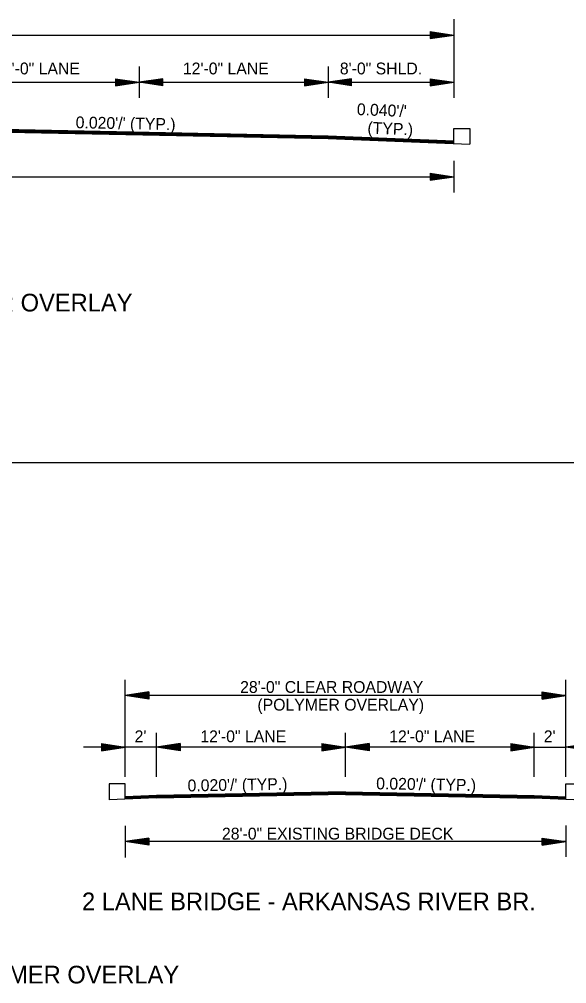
# Model space of a CAD drawing. Extents: x 550980 to 1930787, y -1972975 to 596640.
# Drawn here: x 551685 to 552033, y -1954087 to -1953474 of the extents above; entities that cross this region are included whole.
import ezdxf

# ---------------------------------------------------------------- set-up
doc = ezdxf.new("R2010")
doc.units = 0
doc.layers.add('R_Border', color=7, linetype='Continuous')
doc.layers.add('R_Draft', color=7, linetype='Continuous')

msp = doc.modelspace()

# ---------------------------------------------------------------- linework, layer by layer
at = {"layer": 'R_Border'}
for p, q in [((551961.34, -1953474.37), (551961.34, -1953524.37)), ((551946.34, -1953482.12), (551961.34, -1953484.37)), ((551946.34, -1953482.12), (551946.34, -1953486.62)), ((551946.34, -1953482.5), (551958.83, -1953484.37)), ((551201.34, -1953484.37), (551961.34, -1953484.37)), ((551946.34, -1953482.88), (551956.25, -1953484.37)), ((551946.34, -1953483.25), (551953.76, -1953484.37)), ((551946.34, -1953483.64), (551951.21, -1953484.37)), ((551946.34, -1953484.02), (551948.71, -1953484.37)), ((551946.34, -1953486.62), (551961.34, -1953484.37)), ((551946.34, -1953485.11), (551951.21, -1953484.37)), ((551946.34, -1953485.86), (551956.25, -1953484.37)), ((551946.34, -1953486.25), (551958.83, -1953484.37)), ((551946.34, -1953485.49), (551953.76, -1953484.37)), ((551946.34, -1953484.72), (551948.71, -1953484.37)), ((551761.34, -1953504.37), (551761.34, -1953524.37)), ((551881.34, -1953504.37), (551881.34, -1953524.37)), ((551746.34, -1953512.12), (551761.34, -1953514.37)), ((551746.34, -1953512.12), (551746.34, -1953516.62)), ((551746.34, -1953512.5), (551758.83, -1953514.37)), ((551746.34, -1953512.88), (551756.25, -1953514.37)), ((551776.34, -1953512.12), (551761.34, -1953514.37)), ((551776.34, -1953512.5), (551763.84, -1953514.37)), ((551776.34, -1953512.88), (551766.42, -1953514.37)), ((551776.34, -1953516.62), (551776.34, -1953512.12)), ((551866.34, -1953512.12), (551881.34, -1953514.37)), ((551866.34, -1953512.12), (551866.34, -1953516.62)), ((551866.34, -1953512.5), (551878.83, -1953514.37)), ((551866.34, -1953512.88), (551876.25, -1953514.37)), ((551896.34, -1953512.12), (551881.34, -1953514.37)), ((551896.34, -1953512.5), (551883.84, -1953514.37)), ((551896.34, -1953512.88), (551886.42, -1953514.37)), ((551896.34, -1953516.62), (551896.34, -1953512.12)), ((551946.34, -1953512.12), (551961.34, -1953514.37)), ((551946.34, -1953512.12), (551946.34, -1953516.62)), ((551946.34, -1953512.5), (551958.83, -1953514.37)), ((551946.34, -1953512.88), (551956.25, -1953514.37)), ((551201.34, -1953514.37), (551961.34, -1953514.37)), ((551746.34, -1953513.25), (551753.76, -1953514.37)), ((551746.34, -1953513.64), (551751.21, -1953514.37)), ((551746.34, -1953514.02), (551748.71, -1953514.37)), ((551746.34, -1953516.62), (551761.34, -1953514.37)), ((551746.34, -1953515.11), (551751.21, -1953514.37)), ((551746.34, -1953515.86), (551756.25, -1953514.37)), ((551746.34, -1953516.25), (551758.83, -1953514.37)), ((551746.34, -1953515.49), (551753.76, -1953514.37)), ((551746.34, -1953514.72), (551748.71, -1953514.37)), ((551776.34, -1953516.62), (551761.34, -1953514.37)), ((551776.34, -1953516.25), (551763.84, -1953514.37)), ((551776.34, -1953515.86), (551766.42, -1953514.37)), ((551776.34, -1953513.25), (551768.92, -1953514.37)), ((551776.34, -1953515.49), (551768.92, -1953514.37)), ((551776.34, -1953513.64), (551771.46, -1953514.37)), ((551776.34, -1953515.1), (551771.46, -1953514.37)), ((551776.34, -1953514.02), (551773.97, -1953514.37)), ((551776.34, -1953514.72), (551773.97, -1953514.37)), ((551866.34, -1953513.25), (551873.76, -1953514.37)), ((551866.34, -1953513.64), (551871.21, -1953514.37)), ((551866.34, -1953514.02), (551868.71, -1953514.37)), ((551866.34, -1953516.62), (551881.34, -1953514.37)), ((551866.34, -1953515.11), (551871.21, -1953514.37)), ((551866.34, -1953515.86), (551876.25, -1953514.37)), ((551866.34, -1953516.25), (551878.83, -1953514.37)), ((551866.34, -1953515.49), (551873.76, -1953514.37)), ((551866.34, -1953514.72), (551868.71, -1953514.37)), ((551896.34, -1953516.62), (551881.34, -1953514.37)), ((551896.34, -1953516.25), (551883.84, -1953514.37)), ((551896.34, -1953515.86), (551886.42, -1953514.37)), ((551896.34, -1953513.25), (551888.92, -1953514.37)), ((551896.34, -1953515.49), (551888.92, -1953514.37)), ((551896.34, -1953513.64), (551891.46, -1953514.37)), ((551896.34, -1953515.1), (551891.46, -1953514.37)), ((551896.34, -1953514.02), (551893.97, -1953514.37)), ((551896.34, -1953514.72), (551893.97, -1953514.37)), ((551946.34, -1953513.25), (551953.76, -1953514.37)), ((551946.34, -1953513.64), (551951.21, -1953514.37)), ((551946.34, -1953514.02), (551948.71, -1953514.37)), ((551946.34, -1953516.62), (551961.34, -1953514.37)), ((551946.34, -1953515.11), (551951.21, -1953514.37)), ((551946.34, -1953515.86), (551956.25, -1953514.37)), ((551946.34, -1953516.25), (551958.83, -1953514.37)), ((551946.34, -1953515.49), (551953.76, -1953514.37)), ((551946.34, -1953514.72), (551948.71, -1953514.37)), ((551961.34, -1953553.07), (551961.34, -1953543.66)), ((551961.34, -1953543.66), (551971.51, -1953543.66)), ((551971.51, -1953543.66), (551971.51, -1953553.78)), ((551961.34, -1953564.37), (551961.34, -1953584.37)), ((551201.34, -1953574.37), (551961.34, -1953574.37)), ((551946.34, -1953572.12), (551961.34, -1953574.37)), ((551946.34, -1953572.12), (551946.34, -1953576.62)), ((551946.34, -1953572.5), (551958.83, -1953574.37)), ((551946.34, -1953572.88), (551956.25, -1953574.37)), ((551946.34, -1953573.25), (551953.76, -1953574.37)), ((551946.34, -1953573.64), (551951.21, -1953574.37)), ((551946.34, -1953574.02), (551948.71, -1953574.37)), ((551946.34, -1953576.62), (551961.34, -1953574.37)), ((551946.34, -1953575.11), (551951.21, -1953574.37)), ((551946.34, -1953575.86), (551956.25, -1953574.37)), ((551946.34, -1953576.25), (551958.83, -1953574.37)), ((551946.34, -1953575.49), (551953.76, -1953574.37)), ((551946.34, -1953574.72), (551948.71, -1953574.37)), ((551008.97, -1953755.99), (552070.24, -1953755.99)), ((551742.24, -1953960.14), (551742.24, -1953970.25)), ((551752.41, -1953960.14), (551742.24, -1953960.14)), ((551752.41, -1953969.54), (551752.41, -1953960.14)), ((552032.41, -1953969.54), (552032.41, -1953960.14)), ((552032.41, -1953960.14), (552042.58, -1953960.14))]:
    msp.add_line(p, q, dxfattribs=at)
for points in [[(551201.34, -1953551.57), (551281.34, -1953548.37), (551581.34, -1953542.37), (551881.34, -1953548.37), (551961.34, -1953551.57)], [(551201.34, -1953551.87), (551281.34, -1953548.67), (551581.34, -1953542.67), (551881.34, -1953548.67), (551961.34, -1953551.87)], [(551201.34, -1953552.17), (551281.34, -1953548.97), (551581.34, -1953542.97), (551881.34, -1953548.97), (551961.34, -1953552.17)], [(551201.34, -1953552.47), (551281.34, -1953549.27), (551581.34, -1953543.27), (551881.34, -1953549.27), (551961.34, -1953552.47)], [(551201.34, -1953552.77), (551281.34, -1953549.57), (551581.34, -1953543.57), (551881.34, -1953549.57), (551961.34, -1953552.77)], [(551191.17, -1953553.78), (551281.34, -1953550.17), (551581.34, -1953544.17), (551881.34, -1953550.17), (551971.51, -1953553.78)], [(551201.34, -1953553.07), (551281.34, -1953549.87), (551581.34, -1953543.87), (551881.34, -1953549.87), (551961.34, -1953553.07)]]:
    msp.add_lwpolyline(points, dxfattribs=at)
at = {"layer": 'R_Draft'}
for p, q in [((551752.41, -1953955.6), (551752.41, -1953894.11)), ((552032.41, -1953955.6), (552032.41, -1953894.11)), ((551767.41, -1953901.75), (551752.41, -1953904)), ((552032.41, -1953904), (551752.41, -1953904)), ((551767.41, -1953906.25), (551752.41, -1953904)), ((551767.41, -1953902.13), (551754.92, -1953904)), ((551767.41, -1953905.88), (551754.92, -1953904)), ((551767.41, -1953902.51), (551757.5, -1953904)), ((551767.41, -1953905.49), (551757.5, -1953904)), ((551767.41, -1953902.88), (551759.99, -1953904)), ((551767.41, -1953905.12), (551759.99, -1953904)), ((551767.41, -1953903.27), (551762.54, -1953904)), ((551767.41, -1953904.74), (551762.54, -1953904)), ((551767.41, -1953903.65), (551765.04, -1953904)), ((551767.41, -1953904.35), (551765.04, -1953904)), ((551767.41, -1953901.75), (551767.41, -1953906.25)), ((552017.41, -1953901.75), (552032.41, -1953904)), ((552017.41, -1953906.25), (552017.41, -1953901.75)), ((552017.41, -1953902.13), (552029.91, -1953904)), ((552017.41, -1953902.51), (552027.33, -1953904)), ((552017.41, -1953902.88), (552024.83, -1953904)), ((552017.41, -1953903.27), (552022.29, -1953904)), ((552017.41, -1953903.65), (552019.78, -1953904)), ((552017.41, -1953906.25), (552032.41, -1953904)), ((552017.41, -1953904.73), (552022.29, -1953904)), ((552017.41, -1953905.49), (552027.33, -1953904)), ((552017.41, -1953905.88), (552029.91, -1953904)), ((552017.41, -1953905.12), (552024.83, -1953904)), ((552017.41, -1953904.35), (552019.78, -1953904)), ((551772.41, -1953955.6), (551772.41, -1953927.64)), ((551892.41, -1953955.6), (551892.41, -1953927.64)), ((552012.41, -1953955.6), (552012.41, -1953927.64)), ((551737.41, -1953934.58), (551752.41, -1953936.83)), ((551737.41, -1953934.58), (551737.41, -1953939.08)), ((551737.41, -1953934.96), (551749.91, -1953936.83)), ((551737.41, -1953935.34), (551747.33, -1953936.83)), ((551737.41, -1953935.72), (551744.83, -1953936.83)), ((551787.41, -1953934.58), (551772.41, -1953936.83)), ((551787.41, -1953934.96), (551774.92, -1953936.83)), ((551787.41, -1953935.34), (551777.5, -1953936.83)), ((551787.41, -1953935.72), (551779.99, -1953936.83)), ((551787.41, -1953934.58), (551787.41, -1953939.08)), ((551877.41, -1953934.58), (551892.41, -1953936.83)), ((551877.41, -1953934.58), (551877.41, -1953939.08)), ((551877.41, -1953934.96), (551889.91, -1953936.83)), ((551877.41, -1953935.34), (551887.33, -1953936.83)), ((551877.41, -1953935.72), (551884.83, -1953936.83)), ((551907.41, -1953934.58), (551892.41, -1953936.83)), ((551907.41, -1953934.96), (551894.92, -1953936.83)), ((551907.41, -1953935.34), (551897.5, -1953936.83)), ((551907.41, -1953935.72), (551899.99, -1953936.83)), ((551907.41, -1953934.58), (551907.41, -1953939.08)), ((551997.41, -1953934.58), (552012.41, -1953936.83)), ((551997.41, -1953934.58), (551997.41, -1953939.08)), ((551997.41, -1953934.96), (552009.91, -1953936.83)), ((551997.41, -1953935.34), (552007.33, -1953936.83)), ((551997.41, -1953935.72), (552004.83, -1953936.83)), ((552047.41, -1953934.58), (552032.41, -1953936.83)), ((551752.41, -1953936.83), (551725.89, -1953936.83)), ((551737.41, -1953936.11), (551742.29, -1953936.83)), ((551737.41, -1953936.48), (551739.78, -1953936.83)), ((551737.41, -1953939.08), (551752.41, -1953936.83)), ((551737.41, -1953937.57), (551742.29, -1953936.83)), ((551737.41, -1953938.33), (551747.33, -1953936.83)), ((551737.41, -1953938.71), (551749.91, -1953936.83)), ((551737.41, -1953937.95), (551744.83, -1953936.83)), ((551737.41, -1953937.19), (551739.78, -1953936.83)), ((551772.41, -1953936.83), (551752.41, -1953936.83)), ((551892.41, -1953936.83), (551772.41, -1953936.83)), ((551787.41, -1953939.08), (551772.41, -1953936.83)), ((551787.41, -1953938.71), (551774.92, -1953936.83)), ((551787.41, -1953938.33), (551777.5, -1953936.83)), ((551787.41, -1953937.95), (551779.99, -1953936.83)), ((551787.41, -1953936.11), (551782.54, -1953936.83)), ((551787.41, -1953937.57), (551782.54, -1953936.83)), ((551787.41, -1953936.48), (551785.04, -1953936.83)), ((551787.41, -1953937.19), (551785.04, -1953936.83)), ((551877.41, -1953936.11), (551882.29, -1953936.83)), ((551877.41, -1953936.48), (551879.78, -1953936.83)), ((551877.41, -1953939.08), (551892.41, -1953936.83)), ((551877.41, -1953937.57), (551882.29, -1953936.83)), ((551877.41, -1953938.33), (551887.33, -1953936.83)), ((551877.41, -1953938.71), (551889.91, -1953936.83)), ((551877.41, -1953937.95), (551884.83, -1953936.83)), ((551877.41, -1953937.19), (551879.78, -1953936.83)), ((552012.41, -1953936.83), (551892.41, -1953936.83)), ((551907.41, -1953939.08), (551892.41, -1953936.83)), ((551907.41, -1953938.71), (551894.92, -1953936.83)), ((551907.41, -1953938.33), (551897.5, -1953936.83)), ((551907.41, -1953937.95), (551899.99, -1953936.83)), ((551907.41, -1953936.11), (551902.54, -1953936.83)), ((551907.41, -1953937.57), (551902.54, -1953936.83)), ((551907.41, -1953936.48), (551905.04, -1953936.83)), ((551907.41, -1953937.19), (551905.04, -1953936.83)), ((551997.41, -1953936.11), (552002.29, -1953936.83)), ((551997.41, -1953936.48), (551999.78, -1953936.83)), ((551997.41, -1953939.08), (552012.41, -1953936.83)), ((551997.41, -1953937.57), (552002.29, -1953936.83)), ((551997.41, -1953938.33), (552007.33, -1953936.83)), ((551997.41, -1953938.71), (552009.91, -1953936.83)), ((551997.41, -1953937.95), (552004.83, -1953936.83)), ((551997.41, -1953937.19), (551999.78, -1953936.83)), ((552012.41, -1953936.83), (552032.41, -1953936.83)), ((552047.41, -1953939.08), (552032.41, -1953936.83)), ((552058.93, -1953936.83), (552032.41, -1953936.83)), ((551892.41, -1953965.14), (551772.41, -1953967.54)), ((551892.41, -1953965.44), (551772.41, -1953967.84)), ((551892.41, -1953965.74), (551772.41, -1953968.14)), ((551892.41, -1953966.04), (551772.41, -1953968.44)), ((551892.41, -1953966.34), (551772.41, -1953968.74)), ((551892.41, -1953965.14), (552012.41, -1953967.54)), ((551892.41, -1953965.44), (552012.41, -1953967.84)), ((551892.41, -1953965.74), (552012.41, -1953968.14)), ((551892.41, -1953966.04), (552012.41, -1953968.44)), ((551892.41, -1953966.34), (552012.41, -1953968.74)), ((551772.41, -1953969.04), (551742.24, -1953970.25)), ((551772.41, -1953967.54), (551752.41, -1953968.34)), ((551772.41, -1953967.84), (551752.41, -1953968.64)), ((551772.41, -1953968.14), (551752.41, -1953968.94)), ((551772.41, -1953968.44), (551752.41, -1953969.24)), ((551772.41, -1953968.74), (551752.41, -1953969.54)), ((551892.41, -1953966.64), (551772.41, -1953969.04)), ((551892.41, -1953966.81), (551772.41, -1953969.21)), ((551892.41, -1953966.64), (552012.41, -1953969.04)), ((551892.41, -1953966.81), (552012.41, -1953969.21)), ((552012.41, -1953967.54), (552032.41, -1953968.34)), ((552012.41, -1953967.84), (552032.41, -1953968.64)), ((552012.41, -1953968.14), (552032.41, -1953968.94)), ((552012.41, -1953968.44), (552032.41, -1953969.24)), ((552012.41, -1953968.74), (552032.41, -1953969.54)), ((552012.41, -1953969.04), (552042.58, -1953970.25)), ((551752.41, -1953986.8), (551752.41, -1954006.8)), ((552032.41, -1953986.55), (552032.41, -1954006.55)), ((551767.41, -1953994.55), (551752.41, -1953996.8)), ((551767.41, -1953999.05), (551752.41, -1953996.8)), ((552032.41, -1953996.8), (551752.41, -1953996.8)), ((551767.41, -1953994.93), (551754.92, -1953996.8)), ((551767.41, -1953998.68), (551754.92, -1953996.8)), ((551767.41, -1953995.31), (551757.5, -1953996.8)), ((551767.41, -1953998.29), (551757.5, -1953996.8)), ((551767.41, -1953995.68), (551759.99, -1953996.8)), ((551767.41, -1953997.92), (551759.99, -1953996.8)), ((551767.41, -1953996.07), (551762.54, -1953996.8)), ((551767.41, -1953997.54), (551762.54, -1953996.8)), ((551767.41, -1953996.45), (551765.04, -1953996.8)), ((551767.41, -1953997.15), (551765.04, -1953996.8)), ((551767.41, -1953994.55), (551767.41, -1953999.05)), ((552017.41, -1953994.55), (552032.41, -1953996.8)), ((552017.41, -1953999.05), (552017.41, -1953994.55)), ((552017.41, -1953994.93), (552029.91, -1953996.8)), ((552017.41, -1953995.31), (552027.33, -1953996.8)), ((552017.41, -1953995.68), (552024.83, -1953996.8)), ((552017.41, -1953996.07), (552022.29, -1953996.8)), ((552017.41, -1953996.45), (552019.78, -1953996.8)), ((552017.41, -1953999.05), (552032.41, -1953996.8)), ((552017.41, -1953997.53), (552022.29, -1953996.8)), ((552017.41, -1953998.29), (552027.33, -1953996.8)), ((552017.41, -1953998.68), (552029.91, -1953996.8)), ((552017.41, -1953997.92), (552024.83, -1953996.8)), ((552017.41, -1953997.15), (552019.78, -1953996.8))]:
    msp.add_line(p, q, dxfattribs=at)

# ---------------------------------------------------------------- texts
at = {"layer": 'R_Border'}
for s, height, p in [('12\'-0" LANE', 7.5, (551669.15, -1953509.37)), ('12\'-0" LANE', 7.5, (551789.15, -1953509.37)), ('8\'-0" SHLD.', 7.5, (551888.86, -1953509.37)), ('76 FT. CLEAR ROADWAY BRIDGE - POLYMER OVERLAY', 11.25, (551353.33, -1953660))]:
    msp.add_text(s, height=height, dxfattribs=at).set_placement(p)
for s, rotation, p in [("0.040'/'", 357.7084, (551899.55, -1953535.19)), ("0.020'/' (TYP.)", 358.8542, (551720.95, -1953543.56)), ('(TYP.)', 357.7084, (551906.29, -1953546.97))]:
    msp.add_text(s, height=7.5, rotation=rotation, dxfattribs=at).set_placement(p)
at = {"layer": 'R_Draft'}
for s, height, p in [('28\'-0" CLEAR ROADWAY', 7.5, (551825.5, -1953902.33)), ('(POLYMER OVERLAY)', 7.5, (551836.49, -1953913.58)), ("2'", 7.5, (551758.45, -1953933.66)), ('12\'-0" LANE', 7.5, (551800.23, -1953933.66)), ('12\'-0" LANE', 7.5, (551920.23, -1953933.66)), ("2'", 7.5, (552018.45, -1953933.66)), ('28\'-0" EXISTING BRIDGE DECK', 7.5, (551813.97, -1953995.48)), ('2 LANE BRIDGE - ARKANSAS RIVER BR.', 11.25, (551725.02, -1954040.42)), ('28 FT. CLEAR ROADWAY BRIDGE - POLYMER OVERLAY', 11.25, (551383, -1954086.93))]:
    msp.add_text(s, height=height, dxfattribs=at).set_placement(p)
for rotation, p in [(0.97192, (551792.15, -1953964.94)), (359.02808, (551911.9, -1953963.57))]:
    msp.add_text("0.020'/' (TYP.)", height=7.5, rotation=rotation, dxfattribs=at).set_placement(p)

doc.saveas('drawing.dxf')
